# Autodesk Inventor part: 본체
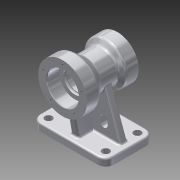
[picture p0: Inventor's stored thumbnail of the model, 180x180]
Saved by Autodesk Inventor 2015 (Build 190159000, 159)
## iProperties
Created: 2015-08
Part Number: 본체
Material: Aluminum 6061
Document SubType Name: Modeling
Designer: 601
Density: 2.7 g/cm^3
Appearance: Aluminum - Flat
Mass: 1057.81 g
Surface Area: 752.357 cm^2
Volume: 391.782 cm^3
Author: 601
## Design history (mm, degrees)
sketch "Sketch1"
  geometry: L1 (-9.843, -7.423)-(112.157, -7.423); L2 (112.157, -7.423)-(112.157, 72.577); L3 (112.157, 72.577)-(-9.843, 72.577); L4 (-9.843, 72.577)-(-9.843, -7.423); L5 (51.157, -7.423)-(51.157, 32.577); L6 (51.157, 32.577)-(4.157, 32.577); L7 (4.157, 32.577)-(4.157, 6.577); C1 r 6 at (4.157, 6.577); C2 r 6 at (4.157, 58.577); C3 r 6 at (98.157, 6.577); C4 r 6 at (98.157, 58.577); 1 further point
  constraints: 14 end point, 4 centre point, 3 perpendicular, 2 horizontal, 2 parallel, 2 vertical, 1 coincident, 1 midpoint, 6 other
  dimensions: "d0" = 122 distance of L3.end L2.end; "d1" = 80 distance of L2.end L1.end; "d2" = 47 distance of L5.end L6.end; "d3" = 26 distance of L6.end L7.end; "d4" = 12 diameter of C1; "d7" = 52 distance of C1.centre C2.centre; "d10" = 94 distance of C1.centre C3.centre
extrude "Extrusion1" new body sketch "Sketch1" distance "d13" = 12; taper "d14" = 0 deg
fillet "Fillet1" dims "d15" = 14
fillet "Fillet2" dims "d16" = 3
workplane "Work Plane1"
workplane "Work Plane2"
sketch "Sketch2"
  geometry: L1 (12, 63)-(12, -11) reference; L2 (9, -14)-(0, -14) reference; L3 (0, -14)-(0, 66) reference; L4 (0, 66)-(9, 66) reference; L5 (0, 26)-(90, 26); L6 (90, -24)-(90, 66); L7 (90, -24)-(130, -24); L8 (130, -24)-(130, -4); L9 (130, -4)-(116, 12.685); L10 (116, 12.685)-(116, 40.804); L11 (116, 40.804)-(125, 46); L12 (125, 46)-(125, 66); L13 (125, 66)-(90, 66); L14 (116, -24)-(116, -4); L15 (106, -1)-(106, 49); L16 (110, 49)-(110, 66); L17 (110, 49)-(109, 49); L18 (116, -4)-(109, -4); L19 (109, 49)-(106, 49); L20 (109, -4)-(109, -1); L21 (109, -1)-(106, -1); A1 r 3 centre (9, 63) between (12, 63) and (9, 66) reference; A2 r 3 centre (9, -11) between (9, -14) and (12, -11) reference; 1 further point
  constraints: 34 end point, 5 horizontal, 4 perpendicular, 2 parallel, 2 point on line, 1 midpoint, 1 vertical
  dimensions: "d17" = 90 distance of L5.start L5.end; "d19" = 90 distance of L6.start L6.end; "d20" = 40 distance of L6.start L7.end; "d21" = 20 distance of L7.end L8.end; "d22" = 40 deg angle of L10 L9; "d23" = 70 diameter of L12 L6; "d24" = 60 deg angle of L10 L11; "d25" = 20 distance of L11.end L12.end; "d26" = 52 diameter of L10 L6; "d28" = 20 distance of L14.start L14.end; "d30" = 40 diameter of L16 L6; "d31" = 32 diameter of L15 L6; "d67" = 52 diameter of L14 L6; "d68" = 17 distance of L16.start L16.end; "d71" = 3 distance of L18.end L20.end; "d72" = 38 diameter of L20 L6
revolve "Revolution1" sketch "Sketch2" stored, may be unused: angle "d37" = 90 deg
sketch "Sketch3"
  geometry: L1 (12, 63)-(12, -11) reference; L2 (9, -14)-(0, -14) reference; L3 (0, -14)-(0, 66) reference; L4 (0, 66)-(9, 66) reference; L5 (130, -24)-(116, -24) reference; L6 (116, -24)-(116, -4) reference; L7 (106, -1)-(106, 49) reference; L8 (106, 49)-(110, 49) reference; L9 (110, 49)-(110, 66) reference; L10 (110, 66)-(125, 66) reference; L11 (125, 66)-(125, 46) reference; L12 (125, 46)-(116, 40.804) reference; L13 (116, 40.804)-(116, 12.685) reference; L14 (116, 12.685)-(130, -4) reference; L15 (130, -4)-(130, -24) reference; L16 (64, -24)-(50, -24) reference; L17 (50, -24)-(50, -4) reference; L18 (50, -4)-(64, 12.685) reference; L19 (64, 12.685)-(64, 40.804) reference; L20 (64, 40.804)-(55, 46) reference; L21 (55, 46)-(55, 66) reference; L22 (55, 66)-(70, 66) reference; L23 (70, 66)-(70, 49) reference; L24 (70, 49)-(74, 49) reference; L25 (74, 49)-(74, -1) reference; L26 (64, -4)-(64, -24) reference; L27 (0, 66)-(0, 56); L28 (0, 56)-(59.5, 56); L29 (0, -14)-(0, -4); L30 (0, -14)-(0, 0) reference; L31 (59.5, 56)-(59.5, 47.894); L32 (59.5, 47.894)-(67.5, 41.734); L33 (67.5, 41.734)-(67.5, 28.442); L34 (3.5, 56)-(4.5, -4.793); L35 (0, -4)-(12, -4); L36 (12, -4)-(53.615, -11.338); L37 (57.644, -14.164)-(53.469, -11.312); L38 (116, -4)-(109, -4) reference; L39 (109, -4)-(109, -1) reference; L40 (109, -1)-(106, -1) reference; L41 (74, -1)-(71, -1) reference; L42 (71, -1)-(71, -4) reference; L43 (71, -4)-(64, -4) reference; L44 (56.117, -13.121)-(58.142, 1.358); L45 (58.142, 1.358)-(66.82, 4.342); L46 (67.5, 28.442)-(66.82, 4.342); A1 r 3 centre (9, 63) between (12, 63) and (9, 66) reference; A2 r 3 centre (9, -11) between (9, -14) and (12, -11) reference; 2 further points
  constraints: 26 end point, 7 point on line, 1 horizontal, 1 parallel, 1 perpendicular, 1 vertical
  dimensions: "d38" = 10 distance of L3.end L27.end; "d39" = 10 distance of L2.end L29.end; "d41" = 80 deg angle of L1 L36
extrude "Extrusion2" join sketch "Sketch3" stored distance "d42" = 12; taper "d43" = 0 deg
sketch "Sketch4"
  geometry: L1 (108, 9)-(108, 0) reference; L2 (108, 0)-(-14, 0) reference; L3 (-14, 0)-(-14, 9) reference; L4 (-11, 12)-(41, 12) reference; L5 (41, 12)-(41, 64.702) reference; L6 (53, 64.702)-(53, 12) reference; L7 (53, 12)-(105, 12) reference; L8 (-14, 0)-(-4, 0); L9 (-4, 0)-(-4, 12); L10 (-4, 12)-(27.255, 97.873); L11 (94, 0)-(0, 0) reference; L12 (98, 12)-(70.107, 88.636); L13 (98, 0)-(98, 12); L14 (27.255, 97.873)-(25.269, 85.56); L15 (25.269, 85.56)-(27.255, 78.776); L16 (27.255, 78.776)-(33.216, 71.605); L17 (33.216, 71.605)-(42.908, 66.565); L18 (42.908, 66.565)-(53, 67.534); L19 (53, 67.534)-(60.235, 69.652); L20 (60.235, 69.652)-(63.115, 75.19); L21 (63.115, 75.19)-(68.725, 79.854); L22 (68.725, 79.854)-(70.107, 88.636); L23 (-4, 6.993)-(98, 6.993); C1 r 16 at (47, 90) reference; A1 r 3 centre (105, 9) between (108, 9) and (105, 12) reference; A2 r 3 centre (-11, 9) between (-11, 12) and (-14, 9) reference; A3 r 26 centre (47, 90) between (53, 64.702) and (41, 64.702) reference; 1 further point
  constraints: 30 end point, 5 point on line, 4 perpendicular, 1 horizontal
  dimensions: "d44" = 10 distance of L2.end L8.end; "d45" = 70 deg angle of L4 L10
extrude "Extrusion3" join sketch "Sketch4" stored distance "d46" = 12; taper "d47" = 0 deg
sketch "Sketch5"
  geometry: L1 (108, 9)-(108, 0) reference; L2 (108, 0)-(-14, 0) reference; L3 (-14, 0)-(-14, 9) reference; L4 (-11, 12)-(-4, 12) reference; L5 (-4, 12)-(21.909, 83.185) reference; L6 (41, 12)-(41, 64.702) reference; L7 (-4, 12)-(41, 12) reference; L8 (98, 12)-(105, 12) reference; L9 (72.091, 83.185)-(98, 12) reference; L10 (53, 64.702)-(53, 12) reference; L11 (53, 12)-(98, 12) reference; L12 (29, 30)-(29, 36.531); L13 (17, 30)-(17.024, 36.023); L14 (94, 0)-(0, 0) reference; L15 (47, 0)-(47, 24); L16 (65, 30)-(65, 36.531); L17 (77, 30)-(76.976, 36.023); C1 r 16 at (47, 90) reference; A1 r 3 centre (105, 9) between (108, 9) and (105, 12) reference; A2 r 3 centre (-11, 9) between (-11, 12) and (-14, 9) reference; A3 r 26 centre (47, 90) between (21.909, 83.185) and (41, 64.702) reference; A4 r 26 centre (47, 90) between (53, 64.702) and (72.091, 83.185) reference; A5 r 26 centre (47, 90) between (72.091, 83.185) and (21.909, 83.185) reference; A6 r 6 centre (23, 30) between (17, 30.047) and (29, 30); A7 r 6 centre (23.024, 36) between (29, 35.469) and (17.024, 36.023); A8 r 6 centre (71, 30) between (65, 30) and (77, 30.047); A9 r 6 centre (70.976, 36) between (76.976, 36.023) and (65, 35.469); 1 further point
  constraints: 14 point on circle, 10 end point, 8 symmetric about line, 4 centre point, 4 point on line, 2 vertical, 1 midpoint, 1 tangent, 2 other
extrude "Extrusion4" cut sketch "Sketch5" stored distance "d53" = 12; taper "d54" = 0 deg
sketch "Sketch6"
  geometry: L1 (0, 0)-(0, 33); C1 r 40 at (0, 0) reference; C2 r 26 at (0, 0) reference; 1 further point
  constraints: 2 end point, 1 vertical
  dimensions: "d55" = 33 distance of L1.start L1.end
hole "Hole1" sketch "Sketch6" at (0, 33) diameter "d56" = 3.242; stored, may be unused: countersink angle "d60" = 90 deg, drill point angle "d62" = 118 deg; dims "d57" = 10, "d58" = 4, "d59" = 2, "d61" = 13
pattern_circular "Circular Pattern1" dims angle "d64" = 360 deg
sketch "Sketch7"
  geometry: L1 (47, 81)-(-47, 81) reference; L2 (-47, 90)-(-47, 81) reference; L3 (-47, 90)-(47, 90) reference; L4 (47, 90)-(47, 81) reference; L5 (0, 0)-(0, -27); C1 r 20 at (0, 0) reference; C2 r 35 at (0, 0) reference; 1 further point
  constraints: 2 end point, 1 vertical
  dimensions: "d66" = 27 distance of L5.start L5.end
hole "Hole2" sketch "Sketch7" at (0, -27) diameter "d73" = 3.242; stored, may be unused: countersink angle "d77" = 90 deg, drill point angle "d79" = 118 deg; dims "d74" = 10, "d75" = 4, "d76" = 2, "d78" = 13
pattern_circular "Circular Pattern2" dims angle "d81" = 360 deg
sketch "Sketch8"
  geometry: L1 (129.547, -4)-(129.547, -24) reference; L2 (129.547, -24)-(115.298, -24) reference; L3 (115.298, -24)-(115.298, -4) reference; L4 (115.298, -4)-(108.028, -4) reference; L5 (108.028, -4)-(108.028, -1) reference; L6 (108.028, -1)-(104.832, -1) reference; L7 (104.832, -1)-(104.832, 49) reference; L8 (104.832, 49)-(109.079, 49) reference; L9 (109.079, 49)-(109.079, 66) reference; L10 (109.079, 66)-(124.482, 66) reference; L11 (124.482, 66)-(124.482, 46) reference; L12 (115.298, 40.804)-(115.298, 12.685) reference; L13 (12, 63)-(12, 56) reference; L14 (12, 56)-(55.518, 56) reference; L15 (55.518, 46)-(55.518, 56) reference; L16 (64.702, 32)-(64.702, 40.804) reference; L17 (12, 32)-(64.702, 32) reference; L18 (12, 56)-(12, 32) reference; L19 (0, 66)-(9, 66) reference; L20 (0, -14)-(0, 66) reference; L21 (9, -14)-(0, -14) reference; L22 (12, -4)-(12, -11) reference; L23 (50.453, -10.78)-(12, -4) reference; L24 (50.453, -10.78)-(50.453, -4) reference; L25 (64.702, 12.685)-(64.702, 20) reference; L26 (64.702, 20)-(12, 20) reference; L27 (12, 20)-(12, -4) reference; L28 (55.518, 56)-(55.518, 66) reference; L29 (55.518, 66)-(70.921, 66) reference; L30 (70.921, 66)-(70.921, 49) reference; L31 (70.921, 49)-(75.168, 49) reference; L32 (75.168, 49)-(75.168, -1) reference; L33 (75.168, -1)-(71.972, -1) reference; L34 (71.972, -1)-(71.972, -4) reference; L35 (71.972, -4)-(64.702, -4) reference; L36 (64.702, -4)-(64.702, -24) reference; L37 (64.702, -24)-(50.453, -24) reference; L38 (50.453, -24)-(50.453, -10.78) reference; L39 (12, 63)-(12, 52) reference; A1 r 3 centre (9, 63) between (12, 63) and (9, 66) reference; A2 r 3 centre (9, -11) between (9, -14) and (12, -11) reference; 2 further points
  constraints: 5 other
emboss "Emboss1" sketch "Sketch8" dims "d0" = 122, "d1" = 80, "d2" = 47, "d3" = 26, "d4" = 12, "d7" = 52, "d10" = 94, "d86" = 0.5, "d87" = 0
fillet "Fillet3" dims "d88" = 5
fillet "Fillet4" dims "d89" = 5
fillet "Fillet5" dims "d90" = 0.3
fillet "Fillet6" dims "d91" = 3
fillet "Fillet7" dims "d92" = 3
fillet "Fillet8" dims "d93" = 3
fillet "Fillet9" dims "d94" = 3
chamfer "Chamfer1" distance "d95" = 1; stored, may be unused: second distance "d96" = 2, angle "d97" = 45 deg
chamfer "Chamfer2" distance "d98" = 1; stored, may be unused: second distance "d99" = 2, angle "d100" = 45 deg
body "Solid1"
node "Project Cut Edges1"
node "Project Cut Edges2"
node "Project Cut Edges3"
node "Project Cut Edges4"
node "Project Cut Edges5"
node "Project Cut Edges6"
node "Project Cut Edges7"
